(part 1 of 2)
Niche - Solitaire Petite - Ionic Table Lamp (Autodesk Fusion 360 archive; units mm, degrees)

design "Marble Base - Ionic Table Lamp - 120V" references "T9-5In", "T8 LED 11", "Arca Tall", "T9 - Bulb", "Facet Petite", "Orb 8.5In - Solitaire Petite", "Neoprene Pad", "Marble Base - Silicone Gasket", "Trove - TL", "Dart", "Rubber Grommet", "Marble Base - Plastic Insert", "Dart Petite", "Chinois", "2-Pole Plug End", "Balon v2"
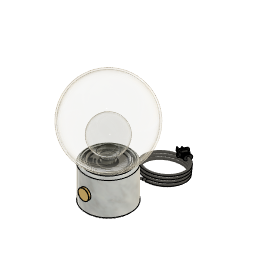
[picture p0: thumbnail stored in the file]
sketch "Sketch1" plane through (0, 0, 0) normal (0, 0, 1) x axis (1, 0, 0)
  circle C1 centre (0, 0) radius 63.5
  point P1 (0, 0)
  point P2 (0, 0)
  coincident P1 P2
extrude "Extrude1" new body sketch "Sketch1" along normal blind 101.6 bodies "Marble Base"
sketch "Sketch2" plane through (0, 0, 101.6) normal (0, 0, 1) x axis (-1, 0, 0)
  circle C1 centre (0, 0) radius 63.5
  circle C2 centre (0, 0) radius 53.975
  concentric C1 C2
  dimension "d3" diameter C2 = 107.95
extrude "Extrude2" cut sketch "Sketch2" profile of C2 against normal blind 34.925
sketch "Sketch3" plane through (0, 0, 66.675) normal (0, 0, 1) x axis (-1, 0, 0)
  circle C1 centre (0, 0) radius 53.975
  circle C2 centre (0, 0) radius 49.276
  point P1 (0, 0)
  point P3 (0, 0)
  coincident P1 P3
  dimension "d6" diameter C2 = 98.552
extrude "Extrude3" cut sketch "Sketch3" profile of C2 against normal blind 45.72
sketch "Sketch4" plane through (0, 0, 0) normal (0, 1, 0) x axis (1, 0, 0)
  circle C1 centre (0, -50.8) radius 3.81
  dimension "d9" diameter C1 = 7.62
extrude "Extrude4" cut sketch "Sketch4" against normal blind 127
sketch "Sketch5" plane through (0, 0, 0) normal (0, 1, 0) x axis (1, 0, 0)
  line L1 (0, -25.4) -> (0, 0)
  line L2 (0, -30.48) -> (0, -25.4)
  circle C1 centre (0, -30.48) radius 5.08
  point P1 (0, 0)
  point P2 (0, 0)
  point P4 (0, -30.48)
  point P5 (0, -30.48)
  coincident P1 P2
  vertical L1
  parallel L1 L2
  coincident P4 P5
  dimension "d12" diameter C1 = 10.16
extrude "Extrude5" cut sketch "Sketch5" profile of C1 along normal blind 114.3
fillet "Fillet1" radius 6.35 3.175 4.064
derived_base_feature "Derived Base Feature1" bodies "Rotary Switch"
derived_base_feature "Derived Base Feature1" bodies "Coiled - SVT (Blk Fabric)"
derived_base_feature "Derived Base Feature1" bodies "Glass Globe"
derived_base_feature "Derived Base Feature1" bodies "Metal Housing"
derived_base_feature "Derived Base Feature1" bodies "Metal Socket Cover"
derived_base_feature "Derived Base Feature1" bodies "Porcelain Socket"
derived_base_feature "Derived Base Feature1" bodies "Brass Dial - Dimmer Knob"
component_from_bodies "Body->Comp1"
offset_faces "OffsetFaces1" distance 12.7
offset_faces "OffsetFaces2" distance -12.7
derived_base_feature "Derived Base Feature1" bodies "Solitaire Petite"
move "Move1"
offset_faces "OffsetFaces1" distance 20.32
move "Move2"
extrude "Extrude6" add of existing geometry blind 25.4
offset_faces "OffsetFaces2" distance -3.81
fillet "Fillet2" radius 2.54
move "Move3"
derived_base_feature "Derived Base Feature2" bodies "Facet Petite"
move "Move4"
offset_faces "OffsetFaces1" distance 2.54
move "Move1"
derived_base_feature "Derived Base Feature1" bodies "Body1"
derived_base_feature "Derived Base Feature1" bodies "Body1"
derived_base_feature "Derived Base Feature1" bodies "Body1"
derived_base_feature "Derived Base Feature1" bodies "Body1"
derived_base_feature "Derived Base Feature1" bodies "Body1"
derived_base_feature "Derived Base Feature1" bodies "Body1", "Body2"
derived_base_feature "Derived Base Feature1" bodies "Body1"
position "Position1"
external_derived "ExternalDerived5" bodies "Plastic Insert"
derived_instance "DerivedInstance15"
offset_faces "OffsetFaces1" distance 3.81
offset_faces "OffsetFaces2" distance -1.0414
move "Move6"
external_derived "ExternalDerived6" sketch "Sketch3" bodies "Silicone Gasket"
derived_instance "DerivedInstance16"
offset_faces "OffsetFaces3" distance -10.795
move "Move1"
move_face "MoveFace1"
position "Position2"
position "Position3"
position "Position4"
position "Position5"
move "Move2"
position "Position6"
offset_faces "OffsetFaces2" distance -7.62
chamfer "Chamfer1" distance 0.381
remove_instance "RemoveInstance1"
remove_instance "RemoveInstance2"
remove_instance "RemoveInstance3"
remove_instance "RemoveInstance4"
move "Move1"
derived_base_feature "Derived Base Feature5" bodies "Oculo Petite"
align "Align1"
external_derived "ExternalDerived8"
derived_base_feature "Derived Base Feature7" bodies "Balon v2"
derived_base_feature "Derived Base Feature8" bodies "Balon v3"
align "Align3"
align "Align4"
external_derived "ExternalDerived10"
component_insert "Component Insert1"
position "Position7"
position "Position8"
derived_base_feature "Derived Base Feature11" bodies "Trove - TL"
move "Move10"
move "Move11"
remove_instance "RemoveInstance5"
split "Split1" bodies "Trove - TL (1)"
remove_body "RemoveBody2"
remove_body "RemoveBody3"
external_derived "ExternalDerived13" bodies "Trove - TL"
derived_instance "DerivedInstance20"
remove_body "RemoveBody4"
remove_body "RemoveBody5"
component_insert "Component Insert2"
component_insert "Component Insert3"
component_from_bodies "Body->Comp2"
remove_body "RemoveBody7"
move "Move12"
move "Move13"
sketch "Sketch6" plane through (0, 0, 97.917) normal (0, 0, 1) x axis (-1, 0, 0)
  circle C1 centre (0, 0) radius 41.275
  circle C2 centre (0, 0) radius 19.685
  arc A1 centre (0, 0) radius 29.3982 clockwise from (-27.6283, 10.0466) to (27.6283, 10.0466)
  arc A2 centre (0, 0) radius 26.2232 clockwise from (-24.6444, 8.9616) to (24.6444, 8.9616)
  arc A3 centre (0, 0) radius 32.5732 clockwise from (-30.6121, 11.1317) to (30.6121, 11.1317)
  arc A4 centre (0, 0) radius 35.7482 clockwise from (-33.596, 12.2167) to (33.596, 12.2167)
  point P1 (0, 0)
  point P3 (0, 0)
  coincident P1 P3
  dimension "d37" = -3.175
  dimension "d38" = 3.175
  dimension "d39" = 6.35
  dimension "d40" Text1-Height = 2.54
  dimension "d41" Text2-Height = 2.54
  dimension "d42" Text3-Height = 2.54
  dimension "d43" Text4-Height = 2.54
extrude "Extrude1" cut sketch "Sketch6" against normal blind 0.254
external_derived "ExternalDerived14" bodies "Rubber Grommet"
derived_instance "DerivedInstance19"
external_derived "ExternalDerived15" bodies "2-Pole Plug End"
derived_instance "DerivedInstance18"
external_derived "ExternalDerived16" bodies "Neoprene Pad"
derived_instance "DerivedInstance17"
position "Position9"
position "Position10"
position "Position11"
position "Position12"
external_derived "ExternalDerived17" bodies "Chinois"
derived_instance "DerivedInstance21"
position "Position13"
move "Move3"
remove_body "RemoveBody8"
component_insert "Component Insert4"
offset_faces "OffsetFaces3" distance 50.8
component_insert "Component Insert5"
position "Position14"
external_derived "ExternalDerived18" bodies "Dart Grand"
derived_instance "DerivedInstance22"
offset_faces "OffsetFaces1" distance -10.16
position "Position15"
external_derived "ExternalDerived19" bodies "Dart Petite"
derived_instance "DerivedInstance23"
offset_faces "OffsetFaces1" distance -10.16
position "Position16"
component_insert "Component Insert6"
position "Position17"
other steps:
derived_base_feature "Derived Base Feature1" bodies "Trove - TL"
derived_base_feature "Derived Base Feature1" bodies "Chinois"
derived_base_feature "Derived Base Feature1" bodies "Dart Grand"
derived_base_feature "Derived Base Feature1" bodies "Dart Petite"
derived_base_feature "Derived Base Feature1" bodies "Rubber Grommet"
derived_base_feature "Derived Base Feature1" bodies "Neoprene Pad"
derived_base_feature "Derived Base Feature1" bodies "2-Pole Plug End"
move "Move1"
derived_base_feature "Derived Base Feature1" bodies "Plastic Insert"
derived_base_feature "Derived Base Feature1" bodies "Silicone Gasket"
base_feature "Base Feature1" bodies "Oculo Petite", "Arca Petite"
base_feature "Base Feature1" bodies "Marble Base"
move "Move8"
derived_base_feature "Derived Base Feature"
create_component "CreateComponent1"
create_component "CreateComponent2"
create_component "CreateComponent3"
create_component "CreateComponent4"
create_component "CreateComponent5"
create_component "CreateComponent6"
create_component "CreateComponent7"
create_component "CreateComponent8"
remove_body "RemoveBody1"
create_component "CreateComponent9"
create_component "CreateComponent10"
create_component "CreateComponent11"
create_component "CreateComponent12"
create_component "CreateComponent13"
create_component "CreateComponent14"
create_component "CreateComponent15"
create_component "CreateComponent16"
create_component "CreateComponent17"
create_component "CreateComponent18"
remove_body "RemoveBody6"
create_component "CreateComponent19"
create_component "CreateComponent20"
create_component "CreateComponent21"
create_component "CreateComponent22"
create_component "CreateComponent23"
create_component "CreateComponent24"
create_component "CreateComponent25"
named bodies: "Marble Base", "Rotary Switch", "Coiled - SVT (Blk Fabric)", "Glass Globe", "Metal Housing", "Metal Socket Cover", "Porcelain Socket", "Brass Dial - Dimmer Knob", "Solitaire Petite", "Facet Petite", "Body1", "Body2", "Plastic Insert", "Silicone Gasket", "Oculo Petite", "Balon v2", "Balon v3", "Trove - TL", "Trove - TL (1)", "Arca Petite", "Neoprene Pad", "2-Pole Plug End", "Rubber Grommet", "Chinois", "Dart Grand", "Dart Petite"

design "Dart Petite"
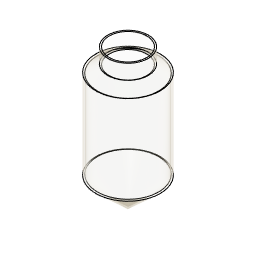
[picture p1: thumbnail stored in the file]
sketch "Sketch1" plane through (0, 0, 0) normal (0, 0, 1) x axis (1, 0, 0)
work_plane "WorkPlane1" AlongDistance 76.2
sketch "Sketch2" plane through (0, 0, 76.2) normal (0, 0, 1) x axis (1, 0, 0)
sketch "Sketch3" plane through (0, 0, 76.2) normal (0, 0, 1) x axis (1, 0, 0)
sketch "Sketch4" plane through (0, 0, 76.2) normal (0, 0, 1) x axis (1, 0, 0)
  circle C1 centre (0, 0) radius 82.55
  point P1 (0, 0)
  point P2 (0, 0)
  coincident P1 P2
  dimension "d2" diameter C1 = 165.1
loft "Loft1" sketch "Sketch4" bodies "Dart Petite"
extrude "Extrude1" add of existing geometry blind 228.6
work_plane "WorkPlane2" AlongDistance 19.05
sketch "Sketch5" plane through (0, 0, 323.85) normal (0, 0, 1) x axis (1, 0, 0)
  circle C1 centre (0, 0) radius 52.07
  point P1 (0, 0)
  point P2 (0, 0)
  coincident P1 P2
  dimension "d6" diameter C1 = 104.14
loft "Loft2" sketch "Sketch5"
extrude "Extrude2" add of existing geometry blind 38.1
shell "Shell3" innerThickness 3.81
component_from_bodies "Body->Comp"
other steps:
base_feature "Base Feature" bodies "Dart Petite"
create_component "CreateComponent1"
remove_body "RemoveBody1"
named bodies: "Dart Petite"

design "Neoprene Pad"
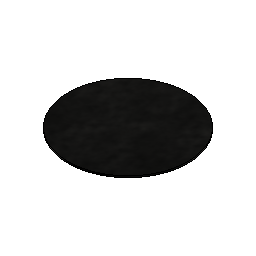
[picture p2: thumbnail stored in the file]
sketch "Sketch1" plane through (0, 0, 0) normal (0, 0, 1) x axis (1, 0, 0)
  circle C1 centre (0, 0) radius 57.15
  point P1 (0, 0)
  point P2 (0, 0)
  coincident P1 P2
extrude "Extrude1" new body sketch "Sketch1" along normal blind 1.5875 bodies "Neoprene Pad"
component_from_bodies "Body->Comp"
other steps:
base_feature "Base Feature" bodies "Neoprene Pad"
create_component "CreateComponent1"
remove_body "RemoveBody1"
named bodies: "Neoprene Pad"

design "T9 - Bulb"
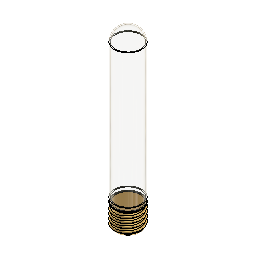
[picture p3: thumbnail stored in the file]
sketch "Sketch1" plane through (0, 0, 0) normal (0, 1, 0) x axis (1, 0, 0)
  line L1 (0, -166.37) -> (0, 0)
  line L2 (13.97, -13.97) -> (13.97, -152.4)
  line L3 (-13.97, -152.4) -> (-13.97, -13.97)
  line L4 (0, 0) -> (0, -166.37)
  line L5 (12.97, -13.97) -> (12.97, -152.4)
  line L6 (-12.97, -152.4) -> (-12.97, -13.97)
  line L7 (-12.3978, -10.16) -> (-13.4404, -10.16)
  line L8 (13.4404, -10.16) -> (12.3978, -10.16)
  arc A1 centre (0, -152.4) radius 13.97 clockwise from (13.97, -152.4) to (-13.97, -152.4)
  arc A2 centre (0, -152.4) radius 12.97 clockwise from (12.97, -152.4) to (-12.97, -152.4)
  arc A3 centre (0, -13.97) radius 13.97 clockwise from (13.4404, -10.16) to (13.97, -13.97)
  arc A4 centre (0, -13.97) radius 13.97 clockwise from (-13.97, -13.97) to (-13.4404, -10.16)
  arc A5 centre (0, -13.97) radius 12.97 clockwise from (12.3978, -10.16) to (12.97, -13.97)
  arc A6 centre (0, -13.97) radius 12.97 clockwise from (-12.97, -13.97) to (-12.3978, -10.16)
  point P1 (0, 0)
  point P2 (0, 0)
  point P3 (0, -166.37)
  point P10 (0, 0)
  point P17 (13.4404, -10.16)
  point P19 (12.3978, -10.16)
  point P4 (13.97, -152.4)
  point P5 (13.97, -13.97)
  coincident P1 P2
  vertical L1
  tangent L2 A3
  tangent L3 A3
  parallel L2 L3
  tangent L3 A1
  tangent L2 A1
  midpoint P3 A1
  coincident P1 P10
  perpendicular L1 L7
  coincident P17 L7
  concentric A3 A4
  coincident P10 A3
  concentric A1 A2
  tangent L5 A2
  tangent L5 A5
  tangent L6 A5
  tangent L6 A2
  coincident P19 L7
  concentric A5 A6
  collinear L7 L8
  dimension "d6" distance L2 L3 = 27.94
  dimension "d7" distance P4 P5 = 138.43
revolve "Revolve1" sketch "Sketch1" AlongAngle 360 bodies "T9"
derived_base_feature "Derived Base Feature" bodies "E26 Base"
align "Align1"
move "Move1"
component_from_bodies "Body->Comp1"
component_from_bodies "Body->Comp2"
copy_paste "CutPaste1"
copy_paste "CutPaste2"
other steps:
base_feature "Base Feature1" bodies "T9"
base_feature "Base Feature1" bodies "E26 Base"
create_component "CreateComponent1"
create_component "CreateComponent2"
remove_body "RemoveBody1"
create_component "CreateComponent3"
remove_body "RemoveBody2"
remove_instance "RemoveInstance1"
remove_instance "RemoveInstance2"
named bodies: "T9", "E26 Base"

design "Facet Petite"
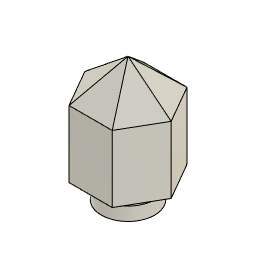
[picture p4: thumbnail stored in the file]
sketch "Sketch7" plane through (0, 0, 0) normal (1, 0, 0) x axis (0, 1, 0)
sketch "Sketch8" plane through (0, 0, 0) normal (0, 0, 1) x axis (1, 0, 0)
  circle C1 centre (0, 0) radius 50.8
  point P1 (0, 0)
  point P2 (0, 0)
  coincident P1 P2
  dimension "d17" diameter C1 = 101.6
extrude "Extrude5" new body sketch "Sketch8" along normal blind 25.4 and against normal blind 25.4
work_plane "WorkPlane1" AlongDistance 17.78
sketch "Sketch10" plane through (0, 0, 25.4) normal (0, 0, 1) x axis (-1, 0, 0)
  circle C1 centre (0, 0) radius 50.8
sketch "Sketch12" plane through (0, 0, 43.18) normal (0, 0, 1) x axis (1, 0, 0)
  line L1 (-82.1223, 0) -> (-41.0612, 71.12)
  line L2 (-41.0612, -71.12) -> (-82.1223, 0)
  line L3 (41.0612, -71.12) -> (-41.0612, -71.12)
  line L4 (82.1223, 0) -> (41.0612, -71.12)
  line L5 (41.0612, 71.12) -> (82.1223, 0)
  line L6 (-41.0612, 71.12) -> (41.0612, 71.12)
  point P1 (0, 0)
  point P8 (0, 0)
  coincident P1 P8
  dimension "d22" distance P8 L6 = 71.12
sketch "Sketch15" plane through (0, 0, 0) normal (0, 1, 0) x axis (1, 0, 0)
  line L1 (53.7365, -21.6801) -> (82.1223, -43.18)
  line L2 (-50.8, -25.4) -> (-82.1223, -43.18)
  point P2 (82.1223, -43.18)
  point P3 (82.1223, -43.18)
  point P5 (-82.1223, -43.18)
  point P7 (-82.1223, -43.18)
  point P6 (-50.8, -25.4)
  point P8 (-50.8, -25.4)
  coincident P2 P3
  coincident P5 P7
  coincident P6 P8
sketch "Sketch17" plane through (0, 0, 25.4) normal (0, 0, 1) x axis (-1, 0, 0)
  line L1 (51.3255, 0) -> (0, 0)
  line L2 (73.3235, 0) -> (0, 0)
  line L3 (-41.0612, -71.12) -> (-25.4, -43.9941)
  line L4 (-36.6617, -63.5) -> (-25.4, -43.9941)
  line L5 (78.4305, 0) -> (0, 0)
  line L6 (41.0612, -71.12) -> (25.4, -43.9941)
  line L7 (25.4, 43.9941) -> (41.0612, 71.12)
  line L8 (73.3235, 0) -> (0, 0)
  line L9 (-25.4, 43.9941) -> (-41.0612, 71.12)
  line L10 (0, 0) -> (0, 0)
  circle C1 centre (0, 0) radius 50.8
  point P1 (0, 0)
  point P4 (0, 0)
  point P2 (-41.0612, -71.12)
  point P6 (-41.0612, -71.12)
  point P3 (0, 0)
  point P7 (0, 0)
  point P9 (-25.4, -43.9941)
  point P12 (41.0612, -71.12)
  point P13 (41.0612, -71.12)
  point P15 (25.4, -43.9941)
  point P16 (41.0612, 71.12)
  point P17 (41.0612, 71.12)
  point P18 (25.4, 43.9941)
  point P19 (-41.0612, 71.12)
  point P20 (-41.0612, 71.12)
  point P21 (0, 0)
  point P23 (-25.4, 43.9941)
  point P25 (0, 0)
  point P24 (0, 0)
  point P26 (0, 0)
  horizontal L1
  coincident P1 P4
  coincident P2 P6
  horizontal L2
  coincident P3 P7
  coincident C1 P9
  coincident P12 P13
  horizontal L5
  coincident C1 P15
  coincident P16 P17
  coincident C1 P18
  coincident P19 P20
  horizontal L8
  coincident P1 P21
  coincident C1 P23
  coincident P1 P25
  coincident P24 P26
extrude "Extrude6" new body sketch "Sketch12" along normal blind 127
work_plane "WorkPlane2" AlongDistance 66.04
sketch "Sketch18" plane through (0, 0, 236.22) normal (0, 0, 1) x axis (1, 0, 0)
  line L1 (41.0612, -71.12) -> (0, 0)
  line L2 (82.1223, 0) -> (0, 0)
  line L3 (41.0612, 71.12) -> (0, 0)
  line L4 (-41.0612, 71.12) -> (0, 0)
  line L5 (-82.1223, 0) -> (0, 0)
  line L6 (-41.0612, -71.12) -> (0, 0)
  point P1 (0, 0)
  point P3 (0, 0)
  point P2 (41.0612, -71.12)
  point P4 (41.0612, -71.12)
  point P6 (0, 0)
  point P5 (82.1223, 0)
  point P7 (82.1223, 0)
  point P9 (0, 0)
  point P8 (41.0612, 71.12)
  point P10 (41.0612, 71.12)
  point P12 (0, 0)
  point P11 (-41.0612, 71.12)
  point P13 (-41.0612, 71.12)
  point P15 (0, 0)
  point P14 (-82.1223, 0)
  point P16 (-82.1223, 0)
  point P18 (0, 0)
  point P17 (-41.0612, -71.12)
  point P19 (-41.0612, -71.12)
  coincident P1 P3
  coincident P2 P4
  coincident P1 P6
  coincident P5 P7
  coincident P1 P9
  coincident P8 P10
  coincident P1 P12
  coincident P11 P13
  coincident P1 P15
  coincident P14 P16
  coincident P1 P18
  coincident P17 P19
loft "Loft1"
loft "Loft2" sketch "Sketch17"
component_from_bodies "Body->Comp"
extrude "Extrude1" cut of existing geometry blind -25.4
shell "Shell2" innerThickness 3.81
fillet "Fillet1" radius 7.62
fillet "Fillet2" radius 6.35
fillet "Fillet3" radius 6.35
fillet "Fillet4" radius 6.35
fillet "Fillet5" radius 6.35
fillet "Fillet6" radius 6.35
fillet "Fillet7" radius 3.81
fillet "Fillet8" radius 6.35
fillet "Fillet9" radius 6.35
fillet "Fillet10" radius 6.35
fillet "Fillet11" radius 6.35
fillet "Fillet12" radius 6.35
fillet "Fillet13" radius 2.286
shell "Shell1" innerThickness 2.54
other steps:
base_feature "Base Feature"
create_component "CreateComponent3"
remove_body "RemoveBody2"

design "Marble Base - Silicone Gasket"
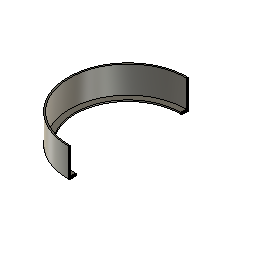
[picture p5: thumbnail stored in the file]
sketch "Sketch1" plane through (0, 0, 0) normal (0, 0, 1) x axis (1, 0, 0)
  circle C1 centre (0, 0) radius 53.34
  point P1 (0, 0)
  point P2 (0, 0)
  coincident P1 P2
extrude "Extrude1" new body sketch "Sketch1" along normal blind 25.4 bodies "Silicone Gasket"
shell "Shell1" innerThickness 1.27
sketch "Sketch2" plane through (0, 0, 1.27) normal (0, 0, 1) x axis (-1, 0, 0)
  circle C1 centre (0, 0) radius 52.07
  circle C2 centre (0, 0) radius 46.99
  concentric C1 C2
extrude "Extrude2" cut sketch "Sketch2" profile of C2 against normal blind 12.7
component_from_bodies "Body->Comp"
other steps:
base_feature "Base Feature" bodies "Silicone Gasket"
create_component "CreateComponent1"
remove_body "RemoveBody1"
named bodies: "Silicone Gasket"

design "Balon v2"
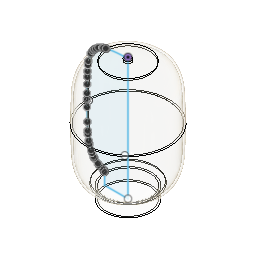
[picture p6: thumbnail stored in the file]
derived_base_feature "Derived Base Feature" bodies "Balon"
work_plane "WorkPlane1" AlongDistance 0
sketch "Sketch1" plane through (0, 0, 0) normal (0, 1, 0) x axis (1, 0, 0)
  line L1 (0, 317.5) -> (0, 2.9083)
  curve K1 (-82.9821, 124.2212) -> (-50.8, 237.8015)
  curve K2 (-51.0925, 237.681) -> (-50.8, 237.8015)
  curve K3 (-51.3855, 237.5558) -> (-51.0925, 237.681)
  curve K4 (-54.7608, 236.0513) -> (-51.3855, 237.5558)
  curve K5 (-57.9615, 234.05) -> (-54.7608, 236.0513)
  curve K6 (-67.2727, 226.749) -> (-57.9615, 234.05)
  curve K7 (-69.0552, 224.2615) -> (-67.2727, 226.749)
  curve K8 (-72.1872, 218.7832) -> (-69.0552, 224.2615)
  curve K9 (-74.1213, 215.1556) -> (-72.1872, 218.7832)
  curve K10 (-78.3031, 204.3965) -> (-74.1213, 215.1556)
  curve K11 (-79.7275, 197.3397) -> (-78.3031, 204.3965)
  curve K12 (-81.3333, 185.4664) -> (-79.7275, 197.3397)
  curve K13 (-81.6254, 178.4008) -> (-81.3333, 185.4664)
  curve K14 (-82.49, 152.2133) -> (-81.6254, 178.4008)
  curve K15 (-82.9821, 136.067) -> (-82.49, 152.2133)
  curve K16 (-82.9821, 124.2212) -> (-82.9821, 136.067)
  curve K17 (50.8, 237.7999) -> (82.9821, 124.2212)
  curve K18 (82.9821, 140.3031) -> (82.9821, 124.2212)
  curve K19 (81.9353, 169.4257) -> (82.9821, 140.3031)
  curve K20 (81.3621, 183.6489) -> (81.9353, 169.4257)
  curve K21 (80.9478, 189.8724) -> (81.3621, 183.6489)
  curve K22 (77.8147, 206.9858) -> (80.9478, 189.8724)
  curve K23 (74.9652, 213.2153) -> (77.8147, 206.9858)
  curve K24 (69.4688, 224.1531) -> (74.9652, 213.2153)
  curve K25 (67.2512, 226.458) -> (69.4688, 224.1531)
  curve K26 (61.5696, 231.3138) -> (67.2512, 226.458)
  curve K27 (57.377, 234.6711) -> (61.5696, 231.3138)
  curve K28 (52.0556, 237.2628) -> (57.377, 234.6711)
  curve K29 (51.4313, 237.5413) -> (52.0556, 237.2628)
  curve K30 (50.8, 237.7999) -> (51.4313, 237.5413)
  line L2 (-50.8, 317.5) -> (-50.8, 237.8015)
  line L3 (50.8, 317.5) -> (50.8, 237.7999)
  line L4 (-19.0713, 6.7501) -> (-19.0713, 6.7501)
  curve K31 (82.9821, 124.1958) -> (40.1509, 7.3012)
  curve K32 (41.8198, 7.6176) -> (40.1509, 7.3012)
  curve K33 (43.2113, 8.0663) -> (41.8198, 7.6176)
  curve K34 (47.0139, 9.2854) -> (43.2113, 8.0663)
  curve K35 (47.3314, 9.3805) -> (47.0139, 9.2854)
  curve K36 (50.1192, 10.3272) -> (47.3314, 9.3805)
  curve K37 (51.833, 11.0085) -> (50.1192, 10.3272)
  curve K38 (57.8313, 14.1895) -> (51.833, 11.0085)
  curve K39 (61.4491, 17.0488) -> (57.8313, 14.1895)
  curve K40 (66.8203, 21.5867) -> (61.4491, 17.0488)
  curve K41 (68.5372, 23.5528) -> (66.8203, 21.5867)
  curve K42 (71.2201, 27.8971) -> (68.5372, 23.5528)
  curve K43 (74.7424, 33.8984) -> (71.2201, 27.8971)
  curve K44 (78.2342, 44.8406) -> (74.7424, 33.8984)
  curve K45 (79.6792, 50.3463) -> (78.2342, 44.8406)
  curve K46 (81.3558, 63.5576) -> (79.6792, 50.3463)
  curve K47 (81.6386, 70.4415) -> (81.3558, 63.5576)
  curve K48 (82.4897, 96.2198) -> (81.6386, 70.4415)
  curve K49 (82.9814, 112.3523) -> (82.4897, 96.2198)
  curve K50 (82.9821, 124.1958) -> (82.9814, 112.3523)
  curve K51 (-40.1501, 7.301) -> (-82.9821, 124.1958)
  curve K52 (-82.9813, 110.5256) -> (-82.9821, 124.1958)
  curve K53 (-82.2545, 88.8594) -> (-82.9813, 110.5256)
  curve K54 (-81.6277, 70.519) -> (-82.2545, 88.8594)
  curve K55 (-81.3572, 64.3441) -> (-81.6277, 70.519)
  curve K56 (-79.4149, 46.8924) -> (-81.3572, 64.3441)
  curve K57 (-76.5204, 38.9768) -> (-79.4149, 46.8924)
  curve K58 (-73.5142, 32.2947) -> (-76.5204, 38.9768)
  curve K59 (-72.5556, 30.3818) -> (-73.5142, 32.2947)
  curve K60 (-69.7914, 25.3691) -> (-72.5556, 30.3818)
  curve K61 (-68.3824, 23.4028) -> (-69.7914, 25.3691)
  curve K62 (-64.5419, 19.5456) -> (-68.3824, 23.4028)
  curve K63 (-62.3002, 17.7646) -> (-64.5419, 19.5456)
  curve K64 (-53.6583, 11.1976) -> (-62.3002, 17.7646)
  curve K65 (-49.6968, 10.1396) -> (-53.6583, 11.1976)
  curve K66 (-43.4141, 8.1331) -> (-49.6968, 10.1396)
  curve K67 (-41.9704, 7.6516) -> (-43.4141, 8.1331)
  curve K68 (-40.1963, 7.3098) -> (-41.9704, 7.6516)
  curve K69 (-40.1732, 7.3054) -> (-40.1963, 7.3098)
  curve K70 (-40.1501, 7.301) -> (-40.1732, 7.3054)
  line L5 (-82.9821, 124.1958) -> (-82.9821, 124.2212)
  line L6 (82.9821, 124.2212) -> (82.9821, 124.1958)
  line L7 (0, 317.5) -> (-50.8, 317.5)
  line L8 (7.2015, 3.048) -> (0, 3.048)
  line L9 (0, 3.048) -> (-7.2015, 3.048)
  arc A1 centre (0, 188.595) radius 185.6867 clockwise from (-7.2015, 3.048) to (-40.1502, 7.301)
  arc A2 centre (0, 188.595) radius 185.6867 clockwise from (40.151, 7.3012) to (7.2015, 3.048)
  point P38 (-40.1502, 7.301)
  point P43 (40.1509, 7.3012)
  point P62 (-40.1501, 7.301)
  point P81 (40.151, 7.3012)
  point P84 (0, 3.048)
  vertical L1
  horizontal L4
  coincident P38 K51
  symmetric L1 A1 A2
  coincident A2 P43
  coincident A1 P62
  coincident K31 P81
  perpendicular L2 L7
  horizontal L8
  coincident L1 P84
  horizontal L9
revolve "Revolve1" sketch "Sketch1" AlongAngle 360
shell "Shell1" innerThickness 3.81
fillet "Fillet1" radius 6.35
offset_faces "OffsetFaces1" distance -50.8
move "Move1"
move "Move2"
component_from_bodies "Body->Comp1"
component_from_bodies "Body->Comp2"
sketch "Sketch2" plane through (0, 0, 0) normal (0, 1, 0) x axis (1, 0, 0)
  line L1 (-85.5221, 124.2212) -> (-85.5221, 124.1961)
  curve K1 (-58.9057, 236.4383) -> (-50.8, 241.7989)
  curve K2 (-50.8, 241.554) -> (-50.8, 241.7989)
  curve K3 (-50.904, 240.933) -> (-50.8, 241.554)
  curve K4 (-51.2936, 240.2837) -> (-50.904, 240.933)
  curve K5 (-51.734, 239.7561) -> (-51.2936, 240.2837)
  curve K6 (-53.328, 238.5038) -> (-51.734, 239.7561)
  curve K7 (-54.0892, 238.1997) -> (-53.328, 238.5038)
  curve K8 (-58.9057, 236.4383) -> (-54.0892, 238.1997)
  curve K9 (-89.3309, 124.2212) -> (-58.9057, 236.4383)
  curve K10 (-62.6336, 234.9735) -> (-58.9057, 236.4383)
  curve K11 (-65.581, 233.1032) -> (-62.6336, 234.9735)
  curve K12 (-73.0224, 227.0019) -> (-65.581, 233.1032)
  curve K13 (-74.8981, 224.836) -> (-73.0224, 227.0019)
  curve K14 (-78.1104, 219.6097) -> (-74.8981, 224.836)
  curve K15 (-80.2663, 215.561) -> (-78.1104, 219.6097)
  curve K16 (-84.0943, 205.8277) -> (-80.2663, 215.561)
  curve K17 (-85.4655, 200.1154) -> (-84.0943, 205.8277)
  curve K18 (-87.4092, 188.5789) -> (-85.4655, 200.1154)
  curve K19 (-87.7349, 182.3889) -> (-87.4092, 188.5789)
  curve K20 (-88.4233, 165.9645) -> (-87.7349, 182.3889)
  curve K21 (-89.328, 138.6964) -> (-88.4233, 165.9645)
  curve K22 (-89.3309, 124.2212) -> (-89.328, 138.6964)
  line L2 (-89.3309, 124.1958) -> (-89.3309, 124.2212)
  curve K23 (-46.5001, 7.301) -> (-89.3309, 124.1958)
  curve K24 (-89.3314, 112.4293) -> (-89.3309, 124.1958)
  curve K25 (-88.8181, 95.3068) -> (-89.3314, 112.4293)
  curve K26 (-88.346, 81.2892) -> (-88.8181, 95.3068)
  curve K27 (-88.0298, 70.4902) -> (-88.346, 81.2892)
  curve K28 (-87.1514, 58.328) -> (-88.0298, 70.4902)
  curve K29 (-86.3326, 50.6119) -> (-87.1514, 58.328)
  curve K30 (-81.0932, 33.6688) -> (-86.3326, 50.6119)
  curve K31 (-77.3163, 27.4309) -> (-81.0932, 33.6688)
  curve K32 (-74.8955, 23.6666) -> (-77.3163, 27.4309)
  curve K33 (-73.5108, 22.0741) -> (-74.8955, 23.6666)
  curve K34 (-70.2346, 19.0457) -> (-73.5108, 22.0741)
  curve K35 (-64.8094, 14.3548) -> (-70.2346, 19.0457)
  curve K36 (-56.6696, 10.3041) -> (-64.8094, 14.3548)
  curve K37 (-54.0053, 9.483) -> (-56.6696, 10.3041)
  curve K38 (-49.1487, 7.9411) -> (-54.0053, 9.483)
  curve K39 (-48.3482, 7.6526) -> (-49.1487, 7.9411)
  curve K40 (-46.5001, 7.301) -> (-48.3482, 7.6526)
  line L3 (0, 266.7) -> (0, 0)
  line L4 (0, 3.048) -> (-7.7894, 3.048)
  line L5 (-50.8, 266.7) -> (-50.8, 241.7989)
  line L6 (0, 266.7) -> (-50.8, 266.7)
  arc A1 centre (-6.9779, 188.7329) radius 185.6867 clockwise from (-7.7894, 3.048) to (-46.5001, 7.301)
  point P1 (0, 0)
  point P44 (0, 0)
  point P46 (0, 3.048)
  point P5 (-50.8, 241.554)
  point P49 (0, 266.7)
  coincident P1 P44
  coincident L3 P46
  coincident P5 L5
  coincident L3 P49
revolve "Revolve2" sketch "Sketch2" AlongAngle 360 bodies "Balon v3"
shell "Shell2" innerThickness 3.81
component_from_bodies "Body->Comp3"
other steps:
base_feature "Base Feature1" bodies "Balon"
base_feature "Base Feature1" bodies "Balon v3"
base_feature "Base Feature1" bodies "Balon v2"
create_component "CreateComponent1"
remove_body "RemoveBody1"
create_component "CreateComponent2"
remove_body "RemoveBody2"
create_component "CreateComponent3"
remove_body "RemoveBody3"
named bodies: "Balon", "Balon v2", "Balon v3"

design "Arca Tall"
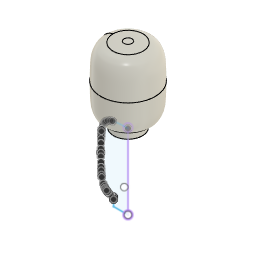
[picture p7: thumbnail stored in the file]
derived_base_feature "Derived Base Feature" bodies "Balon"
work_plane "WorkPlane1" AlongDistance 0
sketch "Sketch1" plane through (0, 0, 0) normal (0, 1, 0) x axis (1, 0, 0)
  line L1 (0, 317.5) -> (0, 2.9083)
  curve K1 (-82.9821, 124.2212) -> (-50.8, 237.8015)
  curve K2 (-51.0925, 237.681) -> (-50.8, 237.8015)
  curve K3 (-51.3855, 237.5558) -> (-51.0925, 237.681)
  curve K4 (-54.7608, 236.0513) -> (-51.3855, 237.5558)
  curve K5 (-57.9615, 234.05) -> (-54.7608, 236.0513)
  curve K6 (-67.2727, 226.749) -> (-57.9615, 234.05)
  curve K7 (-69.0552, 224.2615) -> (-67.2727, 226.749)
  curve K8 (-72.1872, 218.7832) -> (-69.0552, 224.2615)
  curve K9 (-74.1213, 215.1556) -> (-72.1872, 218.7832)
  curve K10 (-78.3031, 204.3965) -> (-74.1213, 215.1556)
  curve K11 (-79.7275, 197.3397) -> (-78.3031, 204.3965)
  curve K12 (-81.3333, 185.4664) -> (-79.7275, 197.3397)
  curve K13 (-81.6254, 178.4008) -> (-81.3333, 185.4664)
  curve K14 (-82.49, 152.2133) -> (-81.6254, 178.4008)
  curve K15 (-82.9821, 136.067) -> (-82.49, 152.2133)
  curve K16 (-82.9821, 124.2212) -> (-82.9821, 136.067)
  curve K17 (50.8, 237.7999) -> (82.9821, 124.2212)
  curve K18 (82.9821, 140.3031) -> (82.9821, 124.2212)
  curve K19 (81.9353, 169.4257) -> (82.9821, 140.3031)
  curve K20 (81.3621, 183.6489) -> (81.9353, 169.4257)
  curve K21 (80.9478, 189.8724) -> (81.3621, 183.6489)
  curve K22 (77.8147, 206.9858) -> (80.9478, 189.8724)
  curve K23 (74.9652, 213.2153) -> (77.8147, 206.9858)
  curve K24 (69.4688, 224.1531) -> (74.9652, 213.2153)
  curve K25 (67.2512, 226.458) -> (69.4688, 224.1531)
  curve K26 (61.5696, 231.3138) -> (67.2512, 226.458)
  curve K27 (57.377, 234.6711) -> (61.5696, 231.3138)
  curve K28 (52.0556, 237.2628) -> (57.377, 234.6711)
  curve K29 (51.4313, 237.5413) -> (52.0556, 237.2628)
  curve K30 (50.8, 237.7999) -> (51.4313, 237.5413)
  line L2 (-50.8, 317.5) -> (-50.8, 237.8015)
  line L3 (50.8, 317.5) -> (50.8, 237.7999)
  line L4 (-19.0713, 6.7501) -> (-19.0713, 6.7501)
  curve K31 (82.9821, 124.1958) -> (40.1509, 7.3012)
  curve K32 (41.8198, 7.6176) -> (40.1509, 7.3012)
  curve K33 (43.2113, 8.0663) -> (41.8198, 7.6176)
  curve K34 (47.0139, 9.2854) -> (43.2113, 8.0663)
  curve K35 (47.3314, 9.3805) -> (47.0139, 9.2854)
  curve K36 (50.1192, 10.3272) -> (47.3314, 9.3805)
  curve K37 (51.833, 11.0085) -> (50.1192, 10.3272)
  curve K38 (57.8313, 14.1895) -> (51.833, 11.0085)
  curve K39 (61.4491, 17.0488) -> (57.8313, 14.1895)
  curve K40 (66.8203, 21.5867) -> (61.4491, 17.0488)
  curve K41 (68.5372, 23.5528) -> (66.8203, 21.5867)
  curve K42 (71.2201, 27.8971) -> (68.5372, 23.5528)
  curve K43 (74.7424, 33.8984) -> (71.2201, 27.8971)
  curve K44 (78.2342, 44.8406) -> (74.7424, 33.8984)
  curve K45 (79.6792, 50.3463) -> (78.2342, 44.8406)
  curve K46 (81.3558, 63.5576) -> (79.6792, 50.3463)
  curve K47 (81.6386, 70.4415) -> (81.3558, 63.5576)
  curve K48 (82.4897, 96.2198) -> (81.6386, 70.4415)
  curve K49 (82.9814, 112.3523) -> (82.4897, 96.2198)
  curve K50 (82.9821, 124.1958) -> (82.9814, 112.3523)
  curve K51 (-40.1501, 7.301) -> (-82.9821, 124.1958)
  curve K52 (-82.9813, 110.5256) -> (-82.9821, 124.1958)
  curve K53 (-82.2545, 88.8594) -> (-82.9813, 110.5256)
  curve K54 (-81.6277, 70.519) -> (-82.2545, 88.8594)
  curve K55 (-81.3572, 64.3441) -> (-81.6277, 70.519)
  curve K56 (-79.4149, 46.8924) -> (-81.3572, 64.3441)
  curve K57 (-76.5204, 38.9768) -> (-79.4149, 46.8924)
  curve K58 (-73.5142, 32.2947) -> (-76.5204, 38.9768)
  curve K59 (-72.5556, 30.3818) -> (-73.5142, 32.2947)
  curve K60 (-69.7914, 25.3691) -> (-72.5556, 30.3818)
  curve K61 (-68.3824, 23.4028) -> (-69.7914, 25.3691)
  curve K62 (-64.5419, 19.5456) -> (-68.3824, 23.4028)
  curve K63 (-62.3002, 17.7646) -> (-64.5419, 19.5456)
  curve K64 (-53.6583, 11.1976) -> (-62.3002, 17.7646)
  curve K65 (-49.6968, 10.1396) -> (-53.6583, 11.1976)
  curve K66 (-43.4141, 8.1331) -> (-49.6968, 10.1396)
  curve K67 (-41.9704, 7.6516) -> (-43.4141, 8.1331)
  curve K68 (-40.1963, 7.3098) -> (-41.9704, 7.6516)
  curve K69 (-40.1732, 7.3054) -> (-40.1963, 7.3098)
  curve K70 (-40.1501, 7.301) -> (-40.1732, 7.3054)
  line L5 (-82.9821, 124.1958) -> (-82.9821, 124.2212)
  line L6 (82.9821, 124.2212) -> (82.9821, 124.1958)
  line L7 (0, 317.5) -> (-50.8, 317.5)
  line L8 (7.2015, 3.048) -> (0, 3.048)
  line L9 (0, 3.048) -> (-7.2015, 3.048)
  arc A1 centre (0, 188.595) radius 185.6867 clockwise from (-7.2015, 3.048) to (-40.1502, 7.301)
  arc A2 centre (0, 188.595) radius 185.6867 clockwise from (40.151, 7.3012) to (7.2015, 3.048)
  point P38 (-40.1502, 7.301)
  point P43 (40.1509, 7.3012)
  point P62 (-40.1501, 7.301)
  point P81 (40.151, 7.3012)
  point P84 (0, 3.048)
  vertical L1
  horizontal L4
  coincident P38 K51
  symmetric L1 A1 A2
  coincident A2 P43
  coincident A1 P62
  coincident K31 P81
  perpendicular L2 L7
  horizontal L8
  coincident L1 P84
  horizontal L9
revolve "Revolve1" sketch "Sketch1" AlongAngle 360
shell "Shell1" innerThickness 3.81
fillet "Fillet1" radius 6.35 bodies "Balon v3"
offset_faces "OffsetFaces1" distance -50.8
move "Move1"
move "Move2"
component_from_bodies "Body->Comp1"
component_from_bodies "Body->Comp2"
sketch "Sketch2" plane through (0, 0, 0) normal (0, 1, 0) x axis (1, 0, 0)
  line L1 (-85.5221, 124.2212) -> (-85.5221, 124.1961)
  curve K1 (-58.9057, 236.4383) -> (-50.8, 241.7989)
  curve K2 (-50.8, 241.554) -> (-50.8, 241.7989)
  curve K3 (-50.904, 240.933) -> (-50.8, 241.554)
  curve K4 (-51.2936, 240.2837) -> (-50.904, 240.933)
  curve K5 (-51.734, 239.7561) -> (-51.2936, 240.2837)
  curve K6 (-53.328, 238.5038) -> (-51.734, 239.7561)
  curve K7 (-54.0892, 238.1997) -> (-53.328, 238.5038)
  curve K8 (-58.9057, 236.4383) -> (-54.0892, 238.1997)
  curve K9 (-89.3309, 124.2212) -> (-58.9057, 236.4383)
  curve K10 (-62.6336, 234.9735) -> (-58.9057, 236.4383)
  curve K11 (-65.581, 233.1032) -> (-62.6336, 234.9735)
  curve K12 (-73.0224, 227.0019) -> (-65.581, 233.1032)
  curve K13 (-74.8981, 224.836) -> (-73.0224, 227.0019)
  curve K14 (-78.1104, 219.6097) -> (-74.8981, 224.836)
  curve K15 (-80.2663, 215.561) -> (-78.1104, 219.6097)
  curve K16 (-84.0943, 205.8277) -> (-80.2663, 215.561)
  curve K17 (-85.4655, 200.1154) -> (-84.0943, 205.8277)
  curve K18 (-87.4092, 188.5789) -> (-85.4655, 200.1154)
  curve K19 (-87.7349, 182.3889) -> (-87.4092, 188.5789)
  curve K20 (-88.4233, 165.9645) -> (-87.7349, 182.3889)
  curve K21 (-89.328, 138.6964) -> (-88.4233, 165.9645)
  curve K22 (-89.3309, 124.2212) -> (-89.328, 138.6964)
  line L2 (-89.3309, 124.1958) -> (-89.3309, 124.2212)
  curve K23 (-46.5001, 7.301) -> (-89.3309, 124.1958)
  curve K24 (-89.3314, 112.4293) -> (-89.3309, 124.1958)
  curve K25 (-88.8181, 95.3068) -> (-89.3314, 112.4293)
  curve K26 (-88.346, 81.2892) -> (-88.8181, 95.3068)
  curve K27 (-88.0298, 70.4902) -> (-88.346, 81.2892)
  curve K28 (-87.1514, 58.328) -> (-88.0298, 70.4902)
  curve K29 (-86.3326, 50.6119) -> (-87.1514, 58.328)
  curve K30 (-81.0932, 33.6688) -> (-86.3326, 50.6119)
  curve K31 (-77.3163, 27.4309) -> (-81.0932, 33.6688)
  curve K32 (-74.8955, 23.6666) -> (-77.3163, 27.4309)
  curve K33 (-73.5108, 22.0741) -> (-74.8955, 23.6666)
  curve K34 (-70.2346, 19.0457) -> (-73.5108, 22.0741)
  curve K35 (-64.8094, 14.3548) -> (-70.2346, 19.0457)
  curve K36 (-56.6696, 10.3041) -> (-64.8094, 14.3548)
  curve K37 (-54.0053, 9.483) -> (-56.6696, 10.3041)
  curve K38 (-49.1487, 7.9411) -> (-54.0053, 9.483)
  curve K39 (-48.3482, 7.6526) -> (-49.1487, 7.9411)
  curve K40 (-46.5001, 7.301) -> (-48.3482, 7.6526)
  line L3 (0, 266.7) -> (0, 0)
  line L4 (0, 3.048) -> (-7.7894, 3.048)
  line L5 (-50.8, 266.7) -> (-50.8, 241.7989)
  line L6 (0, 266.7) -> (-50.8, 266.7)
  arc A1 centre (-6.9779, 188.7329) radius 185.6867 clockwise from (-7.7894, 3.048) to (-46.5001, 7.301)
  point P1 (0, 0)
  point P44 (0, 0)
  point P46 (0, 3.048)
  point P5 (-50.8, 241.554)
  point P49 (0, 266.7)
  coincident P1 P44
  coincident L3 P46
  coincident P5 L5
  coincident L3 P49
revolve "Revolve2" sketch "Sketch2" AlongAngle 360 bodies "Balon v3"
shell "Shell2" innerThickness 3.81
component_from_bodies "Body->Comp3"
remove_instance "RemoveInstance1"
remove_instance "RemoveInstance2"
sketch "Sketch1" plane through (0, 0, 0) normal (0, 1, 0) x axis (1, 0, 0)
  line L1 (-6.35, 3.048) -> (-14.1394, 3.048)
  curve K1 (-52.8501, 7.301) -> (-95.6809, 124.1958)
  curve K2 (-95.6814, 112.4293) -> (-95.6809, 124.1958)
  curve K3 (-95.1681, 95.3068) -> (-95.6814, 112.4293)
  curve K4 (-94.696, 81.2892) -> (-95.1681, 95.3068)
  curve K5 (-94.3798, 70.4902) -> (-94.696, 81.2892)
  curve K6 (-93.5014, 58.328) -> (-94.3798, 70.4902)
  curve K7 (-92.6826, 50.6119) -> (-93.5014, 58.328)
  curve K8 (-87.4432, 33.6688) -> (-92.6826, 50.6119)
  curve K9 (-83.6663, 27.4309) -> (-87.4432, 33.6688)
  curve K10 (-81.2455, 23.6666) -> (-83.6663, 27.4309)
  curve K11 (-79.8608, 22.0741) -> (-81.2455, 23.6666)
  curve K12 (-76.5846, 19.0457) -> (-79.8608, 22.0741)
  curve K13 (-71.12, 13.97) -> (-76.5846, 19.0457)
  curve K14 (-62.23, 10.16) -> (-71.12, 13.97)
  curve K15 (-60.3553, 9.483) -> (-62.23, 10.16)
  curve K16 (-55.4987, 7.9411) -> (-60.3553, 9.483)
  curve K17 (-54.6982, 7.6526) -> (-55.4987, 7.9411)
  curve K18 (-52.8501, 7.301) -> (-54.6982, 7.6526)
  line L2 (-95.6809, 124.1958) -> (-95.6809, 124.2212)
  line L3 (0, 266.7) -> (0, 0)
  line L4 (0, 3.048) -> (-6.35, 3.048)
  line L5 (-95.6809, 124.2466) -> (-95.6809, 124.2212)
  line L6 (-50.8, 266.7) -> (-50.8, 241.7989)
  line L7 (0, 266.7) -> (-50.8, 266.7)
  curve K19 (-71.6837, 232.5587) -> (-50.8, 241.7989)
  curve K20 (-50.8, 237.8015) -> (-50.8, 241.7989)
  curve K21 (-53.6019, 236.5654) -> (-50.8, 237.8015)
  curve K22 (-59.7861, 236.0598) -> (-53.6019, 236.5654)
  curve K23 (-64.4375, 235.2772) -> (-59.7861, 236.0598)
  curve K24 (-69.8917, 233.4707) -> (-64.4375, 235.2772)
  curve K25 (-71.6837, 232.5587) -> (-69.8917, 233.4707)
  curve K26 (-71.6837, 232.5587) -> (-95.6809, 124.2466)
  curve K27 (-95.6814, 136.0132) -> (-95.6809, 124.2466)
  curve K28 (-95.1681, 153.1357) -> (-95.6814, 136.0132)
  curve K29 (-94.696, 167.1533) -> (-95.1681, 153.1357)
  curve K30 (-94.3798, 177.9523) -> (-94.696, 167.1533)
  curve K31 (-93.5014, 190.1145) -> (-94.3798, 177.9523)
  curve K32 (-92.6826, 197.8306) -> (-93.5014, 190.1145)
  curve K33 (-87.4432, 214.7737) -> (-92.6826, 197.8306)
  curve K34 (-83.6663, 221.0115) -> (-87.4432, 214.7737)
  curve K35 (-81.2455, 224.7759) -> (-83.6663, 221.0115)
  curve K36 (-79.8608, 226.3684) -> (-81.2455, 224.7759)
  curve K37 (-77.083, 228.9361) -> (-79.8608, 226.3684)
  curve K38 (-75.5537, 230.2778) -> (-77.083, 228.9361)
  curve K39 (-71.6837, 232.5587) -> (-75.5537, 230.2778)
  curve K40 (-50.8, 244.8458) -> (-50.8, 244.8469)
  curve K41 (-50.8, 244.8465) -> (-50.8, 244.8469)
  curve K42 (-50.8, 244.8462) -> (-50.8, 244.8465)
  curve K43 (-50.8, 244.8458) -> (-50.8, 244.8462)
  arc A1 centre (-13.3279, 188.7329) radius 185.6867 clockwise from (-14.1394, 3.048) to (-52.8501, 7.301)
  point P26 (0, 3.048)
  point P33 (-50.8, 237.8015)
  point P35 (-50.8, 237.8015)
  point P40 (-71.6837, 232.5587)
  point P53 (-50.8, 244.8458)
  coincident L3 P26
  perpendicular L3 L4
  coincident P33 P35
  coincident K19 P40
  coincident L6 P53
sketch "Sketch2" plane through (0, 0, 0) normal (0, 1, 0) x axis (1, 0, 0)
  line L1 (-95.6809, 124.1958) -> (-95.6809, 124.2212)
  line L2 (0, 266.7) -> (-50.8, 266.7)
  curve K1 (-58.9317, 239.3909) -> (-50.8, 244.8469)
  curve K2 (-50.8, 244.602) -> (-50.8, 244.8469)
  curve K3 (-50.904, 243.981) -> (-50.8, 244.602)
  curve K4 (-51.2936, 243.3317) -> (-50.904, 243.981)
  curve K5 (-51.734, 242.8041) -> (-51.2936, 243.3317)
  curve K6 (-53.328, 241.5518) -> (-51.734, 242.8041)
  curve K7 (-54.0892, 241.2477) -> (-53.328, 241.5518)
  curve K8 (-58.9317, 239.3909) -> (-54.0892, 241.2477)
  line L3 (-50.8, 266.7) -> (-50.8, 244.8458)
  curve K9 (-52.8501, 7.301) -> (-95.6809, 124.1958)
  curve K10 (-95.6814, 112.4293) -> (-95.6809, 124.1958)
  curve K11 (-95.1681, 95.3068) -> (-95.6814, 112.4293)
  curve K12 (-94.696, 81.2892) -> (-95.1681, 95.3068)
  curve K13 (-94.3798, 70.4902) -> (-94.696, 81.2892)
  curve K14 (-93.5014, 58.328) -> (-94.3798, 70.4902)
  curve K15 (-92.6826, 50.6119) -> (-93.5014, 58.328)
  curve K16 (-87.4432, 33.6688) -> (-92.6826, 50.6119)
  curve K17 (-83.6663, 27.4309) -> (-87.4432, 33.6688)
  curve K18 (-81.2455, 23.6666) -> (-83.6663, 27.4309)
  curve K19 (-79.8608, 22.0741) -> (-81.2455, 23.6666)
  curve K20 (-76.5846, 19.0457) -> (-79.8608, 22.0741)
  curve K21 (-73.7599, 16.6033) -> (-76.5846, 19.0457)
  curve K22 (-65.532, 11.7145) -> (-73.7599, 16.6033)
  curve K23 (-60.3553, 9.483) -> (-65.532, 11.7145)
  curve K24 (-55.4987, 7.9411) -> (-60.3553, 9.483)
  curve K25 (-54.6982, 7.6526) -> (-55.4987, 7.9411)
  curve K26 (-52.8501, 7.301) -> (-54.6982, 7.6526)
  line L4 (-95.6809, 124.2466) -> (-95.6809, 124.2212)
  line L5 (0, 3.048) -> (-6.35, 3.048)
  line L6 (-6.35, 3.048) -> (-14.1394, 3.048)
  curve K27 (-58.9317, 239.3909) -> (-95.6809, 124.2466)
  curve K28 (-95.6814, 136.0132) -> (-95.6809, 124.2466)
  curve K29 (-95.1681, 153.1357) -> (-95.6814, 136.0132)
  curve K30 (-94.696, 167.1533) -> (-95.1681, 153.1357)
  curve K31 (-94.3798, 177.9523) -> (-94.696, 167.1533)
  curve K32 (-93.5014, 190.1145) -> (-94.3798, 177.9523)
  curve K33 (-92.6826, 197.8306) -> (-93.5014, 190.1145)
  curve K34 (-87.4432, 214.7737) -> (-92.6826, 197.8306)
  curve K35 (-83.6663, 221.0115) -> (-87.4432, 214.7737)
  curve K36 (-81.2455, 224.7759) -> (-83.6663, 221.0115)
  curve K37 (-79.8608, 226.3684) -> (-81.2455, 224.7759)
  curve K38 (-76.5846, 229.3968) -> (-79.8608, 226.3684)
  curve K39 (-73.7599, 231.8391) -> (-76.5846, 229.3968)
  curve K40 (-65.833, 236.5491) -> (-73.7599, 231.8391)
  curve K41 (-61.4585, 238.4785) -> (-65.833, 236.5491)
  curve K42 (-58.9317, 239.3909) -> (-61.4585, 238.4785)
  line L7 (0, 3.048) -> (0, 266.7)
  arc A1 centre (-13.3279, 188.7329) radius 185.6867 clockwise from (-14.1394, 3.048) to (-52.8501, 7.301)
  point P52 (-50.8, 244.8458)
  coincident K1 P52
  perpendicular L5 L7
revolve "Revolve1" sketch "Sketch1" AlongAngle 360 bodies "Balon v3.3"
shell "Shell1" innerThickness 3.81
revolve "Revolve2" sketch "Sketch2" AlongAngle 360 bodies "Balon v3.2"
shell "Shell2" innerThickness 3.81
component_from_bodies "Body->Comp1"
component_from_bodies "Body->Comp2"
position "Position1"
remove_instance "RemoveInstance1" bodies "Balon v3"
remove_instance "RemoveInstance2"
move "Move1"
position "Position2" bodies "Balon v3"
sketch "Sketch3" plane through (0, 0, 0) normal (0, 1, 0) x axis (1, 0, 0)
  line L1 (0, 50.8) -> (0, -304.8)
  line L2 (127, 50.8) -> (127, -304.8)
  line L3 (-127, 50.8) -> (-127, -304.8)
  line L4 (139.7, 25.4) -> (-139.7, 25.4)
  line L5 (139.7, -292.1) -> (-139.7, -292.1)
  line L6 (95.25, 50.8) -> (95.25, -304.8)
  vertical L1
  dimension "d6" = 127
  dimension "d12" = -127
  dimension "d17" distance L4 L5 = 317.5
  dimension "d18" = 95.25
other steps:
base_feature "Base Feature1" bodies "Balon v3.3"
base_feature "Base Feature1" bodies "Balon v3.2"
base_feature "Base Feature1" bodies "Balon"
base_feature "Base Feature1" bodies "Balon v3"
base_feature "Base Feature1" bodies "Balon v2"
create_component "CreateComponent1"
remove_body "RemoveBody1"
create_component "CreateComponent2"
remove_body "RemoveBody2"
create_component "CreateComponent3"
remove_body "RemoveBody3" bodies "Balon v3"
create_component "CreateComponent1"
create_component "CreateComponent2"
remove_body "RemoveBody1" bodies "Balon v3"
create_component "CreateComponent3"
remove_body "RemoveBody2" bodies "Balon v3"
named bodies: "Balon", "Balon v2", "Balon v3", "Balon v3.3", "Balon v3.2"

design "T8 LED 11" references "T9 - Bulb"
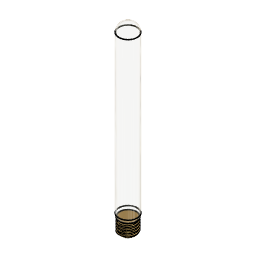
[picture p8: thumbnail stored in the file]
sketch "Sketch1" plane through (0, 0, 0) normal (0, 0, 1) x axis (1, 0, 0)
  circle C1 centre (0, 0) radius 14.986
  point P1 (0, 0)
  point P2 (0, 0)
  coincident P1 P2
  dimension "d1" diameter C1 = 29.972
sketch "Sketch2" plane through (0, 0, 0) normal (0, 1, 0) x axis (1, 0, 0)
  line L1 (0, -273.05) -> (0, 2.54)
  line L2 (15.24, -2.54) -> (15.24, -257.81)
  line L3 (-15.24, -257.81) -> (-15.24, -2.54)
  line L4 (0, 12.7) -> (0, -273.05)
  line L5 (-15.24, 2.54) -> (15.24, 2.54)
  arc A1 centre (0, -2.54) radius 15.24 clockwise from (-15.24, -2.54) to (15.24, -2.54)
  arc A2 centre (0, -257.81) radius 15.24 clockwise from (15.24, -257.81) to (-15.24, -257.81)
  point P2 (0, -273.05)
  point P9 (0, 12.7)
  point P12 (0, 2.54)
  point P1 (0, 0)
  vertical L1
  tangent L2 A1
  tangent A1 L3
  parallel L2 L3
  tangent L3 A2
  tangent L2 A2
  midpoint P2 A2
  midpoint A1 P9
  parallel L1 L4
  horizontal L5
  coincident L5 P12
  dimension "d2" distance P1 P2 = 273.05
revolve "Revolve1" sketch "Sketch2" AlongAngle 360
shell "Shell1" innerThickness 0.9906
external_derived "ExternalDerived1" bodies "E26 Base"
align "Align1"
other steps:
derived_base_feature "Derived Base Feature" bodies "E26 Base"
named bodies: "E26 Base"

design "Chinois"
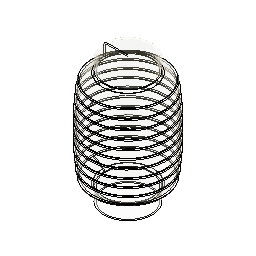
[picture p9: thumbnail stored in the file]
named bodies: "Chinois"

design "2-Pole Plug End"
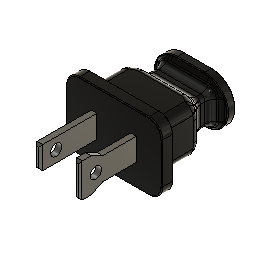
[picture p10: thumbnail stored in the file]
sketch "Sketch1" plane through (0, 0, 0) normal (0, 1, 0) x axis (1, 0, 0)
  line L1 (9.6837, 9.525) -> (-9.6837, 9.525)
  line L2 (13.4938, -5.715) -> (13.4938, 5.715)
  line L3 (-9.6837, -9.525) -> (9.6837, -9.525)
  line L4 (-13.4937, 5.715) -> (-13.4937, -5.715)
  line L5 (13.4938, -9.525) -> (-13.4937, 9.525)
  line L6 (-13.4937, -9.525) -> (13.4938, 9.525)
  arc A1 centre (-9.6837, -5.715) radius 3.81 clockwise from (-9.6837, -9.525) to (-13.4937, -5.715)
  arc A2 centre (9.6837, -5.715) radius 3.81 clockwise from (13.4938, -5.715) to (9.6837, -9.525)
  arc A3 centre (9.6837, 5.715) radius 3.81 clockwise from (9.6837, 9.525) to (13.4938, 5.715)
  arc A4 centre (-9.6837, 5.715) radius 3.81 clockwise from (-13.4937, 5.715) to (-9.6837, 9.525)
  point P6 (0, 0)
  point P1 (0, 0)
  point P5 (-13.4937, -9.525)
  point P4 (13.4938, -9.525)
  point P3 (13.4938, 9.525)
  point P2 (-13.4937, 9.525)
  horizontal L1
  perpendicular L1 L2
  parallel L1 L3
  parallel L2 L4
  coincident L5 P6
  coincident L6 P6
  coincident P1 P6
  coincident P5 L4
  coincident P5 L3
  tangent L4 A1
  tangent L3 A1
  coincident P4 L3
  coincident P4 L2
  tangent L3 A2
  tangent L2 A2
  equal A1 A2
  coincident P3 L2
  coincident P3 L1
  tangent L2 A3
  tangent L1 A3
  equal A1 A3
  coincident P2 L1
  coincident P2 L4
  tangent L1 A4
  tangent L4 A4
  equal A1 A4
  dimension "d1" distance P4 P5 = 26.9875
  dimension "d2" distance P2 P5 = 19.05
  dimension "d3" radius A1 = 3.81
extrude "Extrude1" new body sketch "Sketch1" profile of L1 L2 L3 L4 A1 A2 A3 A4 along normal blind 3.175
sketch "Sketch2" plane through (0, 3.175, 0) normal (0, 1, 0) x axis (-1, 0, 0)
  line L1 (9.6837, -9.525) -> (-9.6837, -9.525)
  line L2 (13.4937, 5.715) -> (13.4937, -5.715)
  line L3 (-9.6837, 9.525) -> (9.6837, 9.525)
  line L4 (-13.4938, -5.715) -> (-13.4938, 5.715)
  line L5 (10.16, -6.35) -> (-10.16, -6.35)
  line L6 (10.16, 6.35) -> (10.16, -6.35)
  line L7 (-10.16, 6.35) -> (10.16, 6.35)
  line L8 (-10.16, -6.35) -> (-10.16, 6.35)
  line L9 (10.16, 6.35) -> (-10.16, -6.35)
  line L10 (-10.16, 6.35) -> (10.16, -6.35)
  arc A1 centre (-9.6837, -5.715) radius 3.81 clockwise from (-9.6837, -9.525) to (-13.4938, -5.715)
  arc A2 centre (9.6837, -5.715) radius 3.81 clockwise from (13.4937, -5.715) to (9.6837, -9.525)
  arc A3 centre (9.6837, 5.715) radius 3.81 clockwise from (9.6837, 9.525) to (13.4937, 5.715)
  arc A4 centre (-9.6837, 5.715) radius 3.81 clockwise from (-13.4938, 5.715) to (-9.6837, 9.525)
  point P18 (0, 0)
  point P1 (0, 0)
  horizontal L5
  perpendicular L5 L6
  parallel L5 L7
  parallel L6 L8
  coincident L9 P18
  coincident L10 P18
  coincident P1 P18
extrude "Extrude2" add sketch "Sketch2" profile of L5 L6 L7 L8 along normal blind 9.525
sketch "Sketch3" plane through (0, 12.7, 0) normal (0, 1, 0) x axis (-1, 0, 0)
  line L1 (-10.16, -6.35) -> (-10.16, 6.35)
  line L2 (10.16, -6.35) -> (-10.16, -6.35)
  line L3 (10.16, 6.35) -> (10.16, -6.35)
  line L4 (-10.16, 6.35) -> (10.16, 6.35)
  line L5 (-7.1437, 3.9688) -> (7.1437, 3.9688)
  line L6 (-7.1437, -3.9688) -> (-7.1437, 3.9688)
  line L7 (7.1437, -3.9688) -> (-7.1437, -3.9688)
  line L8 (7.1437, 3.9688) -> (7.1437, -3.9688)
  line L9 (-7.1437, -3.9688) -> (7.1437, 3.9688)
  line L10 (7.1437, -3.9688) -> (-7.1437, 3.9688)
  point P10 (0, 0)
  point P1 (0, 0)
  point P8 (-7.1437, -3.9688)
  point P9 (7.1437, -3.9688)
  point P7 (-7.1437, 3.9688)
  horizontal L5
  perpendicular L5 L6
  parallel L5 L7
  parallel L6 L8
  coincident L9 P10
  coincident L10 P10
  coincident P1 P10
  dimension "d8" distance P8 P9 = 14.2875
  dimension "d9" distance P7 P8 = 7.9375
extrude "Extrude3" add sketch "Sketch3" profile of L5 L6 L7 L8 along normal blind 11.1125
fillet "Fillet1" radius 2.286 1.27 0.254
chamfer "Chamfer1" distance 3.429
fillet "Fillet2" radius 2.54 1.905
